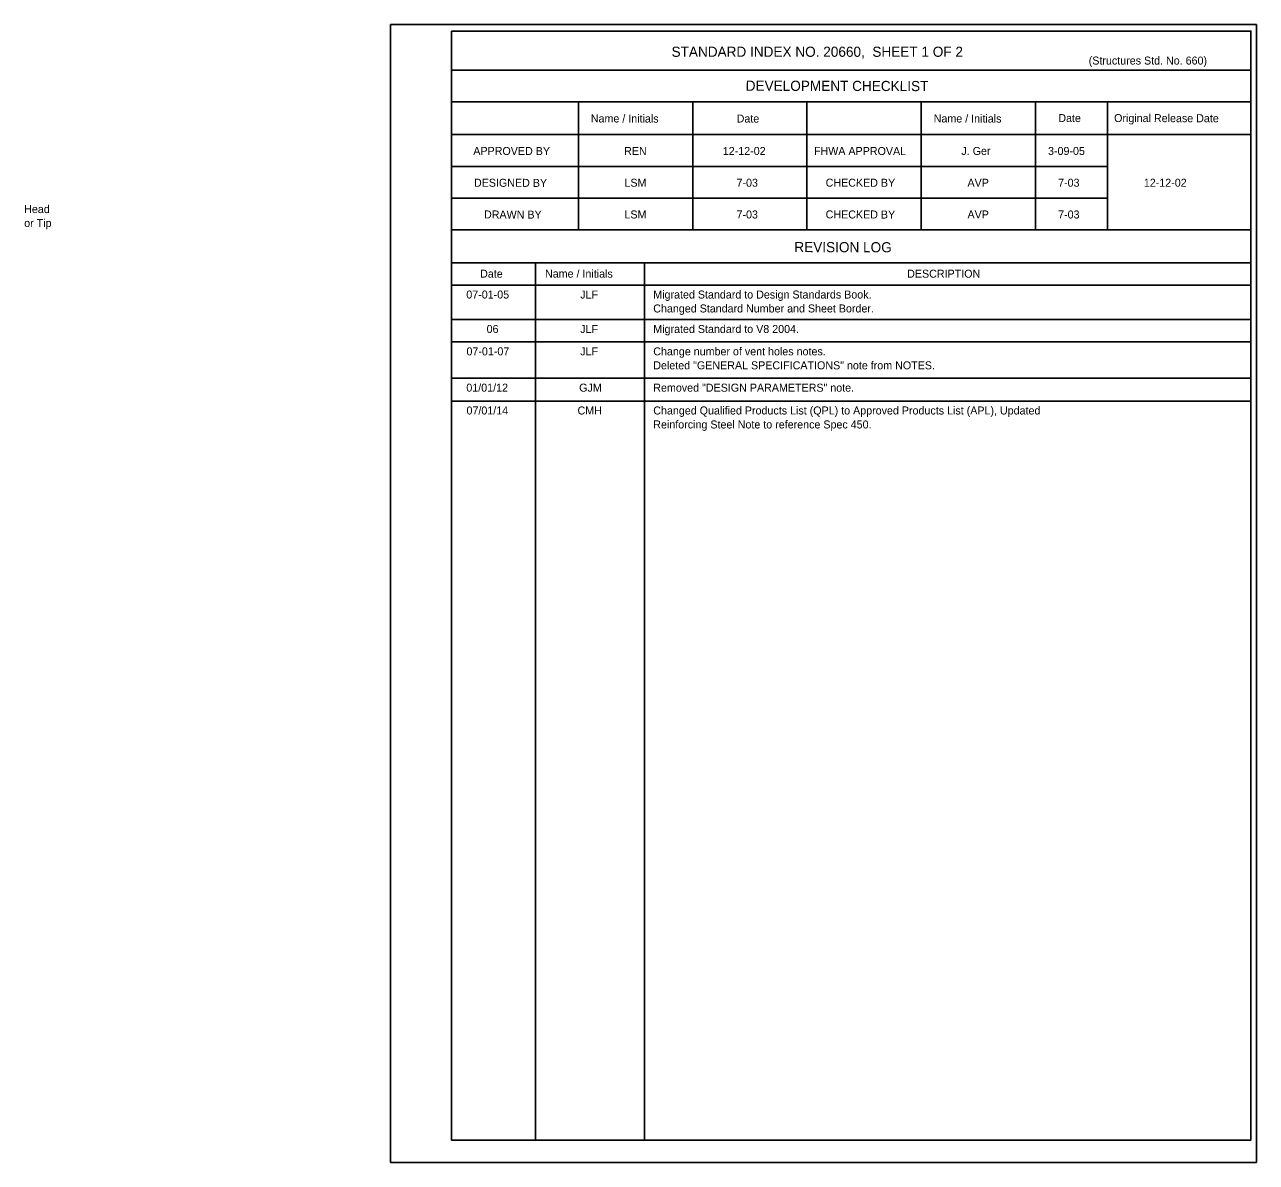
# Model space of a CAD drawing. Extents: x 120519.5 to 120592, y 120600.7 to 120635.1.
# Drawn here: x 120560.97 to 120592.01, y 120600.69 to 120629.36 of the extents above; entities that cross this region are included whole.
import ezdxf

# ---------------------------------------------------------------- set-up
doc = ezdxf.new("R2010")
doc.units = 0
for name, color, linetype in [('Border', 7, 'Continuous'), ('Dimension', 7, 'Continuous'), ('PlotBorder_dp', 7, 'Continuous'), ('TextStructures', 7, 'Continuous')]:
    doc.layers.add(name, color=color, linetype=linetype)

msp = doc.modelspace()

# ---------------------------------------------------------------- linework, layer by layer
at = {"layer": 'Border'}
for p, q in [((120591.874, 120628.217), (120571.727, 120628.217)), ((120591.874, 120627.417), (120571.727, 120627.417)), ((120574.927, 120627.417), (120574.927, 120624.189)), ((120577.807, 120627.417), (120577.807, 120624.189)), ((120580.687, 120627.417), (120580.687, 120624.189)), ((120583.567, 120627.417), (120583.567, 120624.189)), ((120586.447, 120627.417), (120586.447, 120624.189)), ((120588.262, 120627.417), (120588.262, 120624.189)), ((120591.874, 120626.589), (120571.727, 120626.589)), ((120588.262, 120625.789), (120571.727, 120625.789)), ((120588.262, 120624.989), (120571.727, 120624.989)), ((120591.874, 120624.189), (120571.727, 120624.189)), ((120591.874, 120623.361), (120571.727, 120623.361)), ((120573.848, 120623.361), (120573.848, 120601.255)), ((120576.59, 120623.361), (120576.59, 120601.255)), ((120591.874, 120622.797), (120571.727, 120622.797))]:
    msp.add_line(p, q, dxfattribs=at)
msp.add_lwpolyline([(120571.728, 120629.197), (120591.874, 120629.197), (120591.874, 120601.255), (120571.728, 120601.255)], close=True, dxfattribs=at)
at = {"layer": 'Dimension'}
for p, q in [((120571.728, 120621.929), (120591.874, 120621.929)), ((120571.728, 120621.365), (120591.874, 120621.365)), ((120571.728, 120620.45), (120591.874, 120620.45)), ((120571.728, 120619.875), (120591.874, 120619.875))]:
    msp.add_line(p, q, dxfattribs=at)
at = {"layer": 'PlotBorder_dp'}
msp.add_line((120570.197, 120600.693), (120570.197, 120600.693), dxfattribs=at)
msp.add_lwpolyline([(120570.197, 120629.36), (120592.01, 120629.36), (120592.01, 120600.693), (120570.197, 120600.693)], close=True, dxfattribs=at)

# ---------------------------------------------------------------- texts
at = {"layer": 'Dimension'}
for s, p in [('Head', (120560.963, 120624.612)), ('or Tip', (120560.963, 120624.26))]:
    msp.add_text(s, height=0.2016, dxfattribs=at).set_placement(p)
at = {"layer": 'TextStructures'}
for s, height, p in [('STANDARD INDEX NO. 20660,  SHEET 1 OF 2', 0.256, (120577.274, 120628.549)), ('(Structures Std. No. 660)', 0.2016, (120587.786, 120628.354)), ('REN', 0.2016, (120576.079, 120626.076)), ('12-12-02', 0.2016, (120578.566, 120626.076)), ('J. Ger', 0.2016, (120584.577, 120626.076)), ('3-09-05', 0.2016, (120586.761, 120626.076)), ('LSM', 0.2016, (120576.088, 120625.276)), ('7-03', 0.2016, (120578.912, 120625.276)), ('AVP', 0.2016, (120584.731, 120625.276)), ('7-03', 0.2016, (120587.015, 120625.276)), ('12-12-02', 0.2016, (120589.175, 120625.276)), ('LSM', 0.2016, (120576.088, 120624.476)), ('7-03', 0.2016, (120578.912, 120624.476)), ('AVP', 0.2016, (120584.731, 120624.476)), ('7-03', 0.2016, (120587.015, 120624.476)), ('DESCRIPTION', 0.2016, (120583.211, 120622.984)), ('07-01-05', 0.2016, (120572.103, 120622.459)), ('JLF', 0.2016, (120574.974, 120622.459)), ('Migrated Standard to Design Standards Book.', 0.2016, (120576.814, 120622.459)), ('Changed Standard Number and Sheet Border.', 0.2016, (120576.814, 120622.108)), ('06', 0.2016, (120572.615, 120621.591)), ('JLF', 0.2016, (120574.974, 120621.591)), ('Migrated Standard to V8 2004.', 0.2016, (120576.814, 120621.591)), ('07-01-07', 0.2016, (120572.107, 120621.027)), ('JLF', 0.2016, (120574.974, 120621.027)), ('Change number of vent holes notes.', 0.2016, (120576.814, 120621.027)), ('Deleted "GENERAL SPECIFICATIONS" note from NOTES.', 0.2016, (120576.814, 120620.675)), ('01/01/12', 0.2016, (120572.104, 120620.112)), ('GJM', 0.2016, (120574.947, 120620.112)), ('Removed "DESIGN PARAMETERS" note.', 0.2016, (120576.814, 120620.112)), ('07/01/14', 0.2016, (120572.108, 120619.537)), ('CMH', 0.2016, (120574.906, 120619.537)), ('Changed Qualified Products List (QPL) to Approved Products List (APL), Updated', 0.2016, (120576.814, 120619.537)), ('Reinforcing Steel Note to reference Spec 450.', 0.2016, (120576.814, 120619.185))]:
    msp.add_text(s, height=height, dxfattribs=at).set_placement(p)
for s, height, p in [('DEVELOPMENT CHECKLIST', 0.256, (120579.143, 120627.694)), ('Name / Initials', 0.2016, (120575.24, 120626.896)), ('Date', 0.2016, (120578.915, 120626.894)), ('Name / Initials', 0.2016, (120583.88, 120626.896)), ('Date', 0.2016, (120587.02, 120626.906)), ('Original Release Date', 0.2016, (120588.426, 120626.906)), ('APPROVED BY', 0.2016, (120572.279, 120626.078)), ('FHWA APPROVAL', 0.2016, (120580.863, 120626.078)), ('DESIGNED BY', 0.2016, (120572.296, 120625.276)), ('CHECKED BY', 0.2016, (120581.157, 120625.278)), ('DRAWN BY', 0.2016, (120572.549, 120624.476)), ('CHECKED BY', 0.2016, (120581.157, 120624.478)), ('REVISION LOG', 0.256, (120580.369, 120623.628)), ('Date', 0.2016, (120572.45, 120622.985)), ('Name / Initials', 0.2016, (120574.086, 120622.987))]:
    msp.add_text(s, height=height, rotation=359.8756, dxfattribs=at).set_placement(p)

doc.saveas('drawing.dxf')
